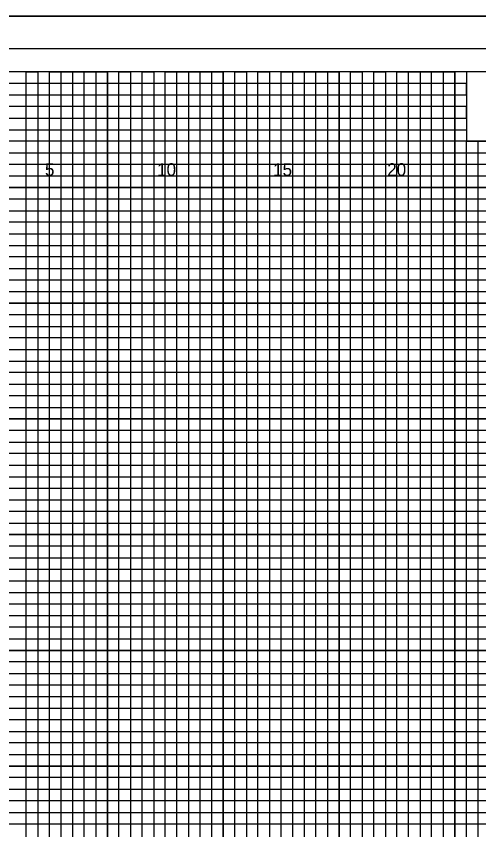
# Model space of a CAD drawing. Extents: x -4 to 103, y -2 to 67.
# Drawn here: x 54.82 to 74.78, y 32.25 to 67.4 of the extents above; entities that cross this region are included whole.
import ezdxf

# ---------------------------------------------------------------- set-up
doc = ezdxf.new("R2010")
doc.units = 0
for name, color, linetype in [('Old_Level_10', 7, 'Continuous'), ('Old_Level_16', 7, 'Continuous'), ('Old_Level_3', 7, 'Continuous'), ('Old_Level_5', 7, 'Continuous'), ('Old_Level_8', 7, 'Continuous'), ('Prop XS Dump Level', 7, 'Continuous'), ('Prop XS Subgrade Concrete', 7, 'Continuous'), ('Typical Curb CELL', 7, 'Continuous')]:
    doc.layers.add(name, color=color, linetype=linetype)

msp = doc.modelspace()

# ---------------------------------------------------------------- linework, layer by layer
at = {"layer": 'Old_Level_10'}
for p, q in [((56.25, 0), (56.25, 65)), ((58.75, 0), (58.75, 65)), ((61.25, 0), (61.25, 65)), ((63.75, 0), (63.75, 65)), ((66.25, 0), (66.25, 65)), ((68.75, 0), (68.75, 65)), ((71.25, 0), (71.25, 65)), ((73.75, 0), (73.75, 65)), ((0, 62.5), (74.25, 62.5)), ((0, 60), (102.5, 60)), ((0, 57.5), (102.5, 57.5)), ((0, 55), (102.5, 55)), ((0, 52.5), (102.5, 52.5)), ((0, 50), (102.5, 50)), ((0, 47.5), (102.5, 47.5)), ((0, 45), (102.5, 45)), ((0, 42.5), (102.5, 42.5)), ((0, 40), (102.5, 40)), ((0, 37.5), (102.5, 37.5)), ((0, 35), (102.5, 35)), ((0, 32.5), (102.5, 32.5))]:
    msp.add_line(p, q, dxfattribs=at)
at = {"layer": 'Old_Level_3'}
msp.add_line((-3.5, 67.4), (103.4, 67.4), dxfattribs=at)
at = {"layer": 'Old_Level_5'}
msp.add_lwpolyline([(103.4, 67.4), (-3.5, 67.4), (-3.5, -2.425), (103.4, -2.425)], close=True, dxfattribs=at)
at = {"layer": 'Old_Level_8'}
for points in [[(56.25, 0), (56.25, 65), (58.75, 65), (58.75, 0)], [(61.25, 0), (61.25, 65), (63.75, 65), (63.75, 0)], [(66.25, 0), (66.25, 65), (68.75, 65), (68.75, 0)], [(71.25, 0), (71.25, 65), (73.75, 65), (73.75, 0)], [(0, 62.5), (74.25, 62.5)], [(0, 57.5), (102.5, 57.5), (102.5, 60), (0, 60)], [(0, 52.5), (102.5, 52.5), (102.5, 55), (0, 55)], [(0, 47.5), (102.5, 47.5), (102.5, 50), (0, 50)], [(0, 42.5), (102.5, 42.5), (102.5, 45), (0, 45)], [(0, 37.5), (102.5, 37.5), (102.5, 40), (0, 40)], [(0, 32.5), (102.5, 32.5), (102.5, 35), (0, 35)]]:
    msp.add_lwpolyline(points, dxfattribs=at)
at = {"layer": 'Prop XS Dump Level'}
for points in [[(55.25, 0), (55.25, 65), (55.75, 65), (55.75, 0)], [(56.75, 0), (56.75, 65), (57.25, 65), (57.25, 0)], [(57.75, 0), (57.75, 65), (58.25, 65), (58.25, 0)], [(59.25, 0), (59.25, 65), (59.75, 65), (59.75, 0)], [(60.25, 0), (60.25, 65), (60.75, 65), (60.75, 0)], [(61.75, 0), (61.75, 65), (62.25, 65), (62.25, 0)], [(62.75, 0), (62.75, 65), (63.25, 65), (63.25, 0)], [(64.25, 0), (64.25, 65), (64.75, 65), (64.75, 0)], [(65.25, 0), (65.25, 65), (65.75, 65), (65.75, 0)], [(66.75, 0), (66.75, 65), (67.25, 65), (67.25, 0)], [(67.75, 0), (67.75, 65), (68.25, 65), (68.25, 0)], [(69.25, 0), (69.25, 65)], [(69.25, 65), (69.75, 65), (69.75, 0)], [(70.25, 0), (70.25, 65), (70.75, 65), (70.75, 0)], [(71.75, 0), (71.75, 65), (72.25, 65), (72.25, 0)], [(72.75, 0), (72.75, 65), (73.25, 65), (73.25, 0)], [(0, 62), (0, 63), (74.25, 63), (74.25, 63.5), (0, 63.5), (0, 64), (74.25, 64), (74.25, 64.5), (0, 64.5)], [(0, 61.5), (102.5, 61.5), (102.5, 62), (0, 62)], [(74.25, 0), (74.25, 62), (74.75, 62), (74.75, 0)], [(0, 60.5), (102.5, 60.5), (102.5, 61), (0, 61)], [(0, 59), (102.5, 59), (102.5, 59.5), (0, 59.5)], [(0, 58), (102.5, 58), (102.5, 58.5), (0, 58.5)], [(0, 56.5), (102.5, 56.5), (102.5, 57), (0, 57)], [(0, 55.5), (102.5, 55.5), (102.5, 56), (0, 56)], [(0, 54), (102.5, 54), (102.5, 54.5), (0, 54.5)], [(0, 53), (102.5, 53), (102.5, 53.5), (0, 53.5)], [(0, 51.5), (102.5, 51.5), (102.5, 52), (0, 52)], [(0, 50.5), (102.5, 50.5), (102.5, 51), (0, 51)], [(0, 49), (102.5, 49), (102.5, 49.5), (0, 49.5)], [(0, 48), (102.5, 48), (102.5, 48.5), (0, 48.5)], [(0, 46.5), (102.5, 46.5), (102.5, 47), (0, 47)], [(0, 45.5), (102.5, 45.5), (102.5, 46), (0, 46)], [(0, 44), (102.5, 44), (102.5, 44.5), (0, 44.5)], [(0, 43), (102.5, 43), (102.5, 43.5), (0, 43.5)], [(0, 41.5), (102.5, 41.5), (102.5, 42), (0, 42)], [(0, 40.5), (102.5, 40.5), (102.5, 41), (0, 41)], [(0, 39), (102.5, 39), (102.5, 39.5), (0, 39.5)], [(0, 38), (102.5, 38), (102.5, 38.5), (0, 38.5)], [(0, 36.5), (102.5, 36.5), (102.5, 37), (0, 37)], [(0, 35.5), (102.5, 35.5), (102.5, 36), (0, 36)], [(0, 34), (102.5, 34), (102.5, 34.5), (0, 34.5)], [(0, 33), (102.5, 33), (102.5, 33.5), (0, 33.5)]]:
    msp.add_lwpolyline(points, dxfattribs=at)
at = {"layer": 'Prop XS Subgrade Concrete'}
for points in [[(102.5, 65), (0, 65), (0, 0), (102.5, 0)], [(83.75, 65), (74.25, 65), (74.25, 62), (83.75, 62)]]:
    msp.add_lwpolyline(points, close=True, dxfattribs=at)
at = {"layer": 'Typical Curb CELL'}
msp.add_lwpolyline([(103, 66), (-2.8, 66), (-2.8, -1), (103, -1)], close=True, dxfattribs=at)

# ---------------------------------------------------------------- texts
at = {"layer": 'Old_Level_16'}
for s, p in [('5', (56.0574, 60.5)), ('10', (60.8971, 60.5)), ('15', (65.9057, 60.5)), ('20', (70.8312, 60.5))]:
    msp.add_text(s, height=0.55, dxfattribs=at).set_placement(p)

doc.saveas('drawing.dxf')
